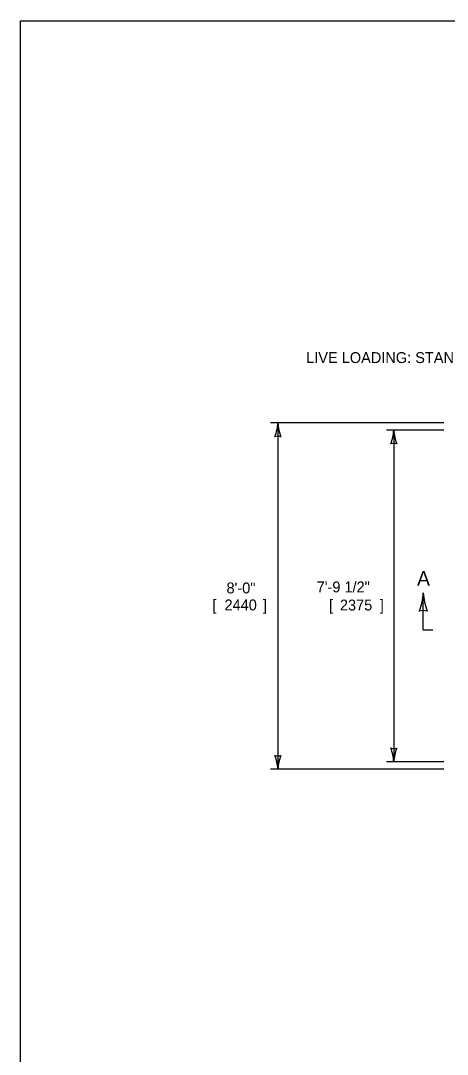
# Model space of a CAD drawing. Extents: x 49991.4 to 50021, y 49987.6 to 50011.4.
# Drawn here: x 49999.38 to 50001.74, y 49993.3 to 49999 of the extents above; entities that cross this region are included whole.
import ezdxf

# ---------------------------------------------------------------- set-up
doc = ezdxf.new("R2010")
doc.units = 0
for name, color, linetype in [('Level 1', 7, 'Continuous'), ('Level 2', 7, 'Continuous'), ('Level 3', 7, 'Continuous'), ('Level 6', 7, 'Continuous')]:
    doc.layers.add(name, color=color, linetype=linetype)

msp = doc.modelspace()

# ---------------------------------------------------------------- linework, layer by layer
at = {"layer": 'Level 1'}
msp.add_lwpolyline([(49999.3835, 49998.9992), (50016.7501, 49998.9992), (50016.7501, 49987.7988), (49999.3835, 49987.7988)], close=True, dxfattribs=at)
at = {"layer": 'Level 3'}
for p, q in [((50001.7187, 49996.781), (50000.7634, 49996.781)), ((50000.8034, 49996.781), (50000.8034, 49994.8717)), ((50001.7187, 49996.741), (50001.403, 49996.741)), ((50001.443, 49996.741), (50001.443, 49994.9122)), ((50001.7187, 49994.8717), (50000.7634, 49994.8717)), ((50001.7187, 49994.9122), (50001.403, 49994.9122))]:
    msp.add_line(p, q, dxfattribs=at)
for centre, radius, start, end in [((50000.5813, 49996.7902), 0.2223, 337.456, 357.6395), ((50001.0362, 49996.7925), 0.233, 182.8273, 202.0772), ((50001.2208, 49996.7502), 0.2223, 337.456, 357.6395), ((50001.6757, 49996.7525), 0.233, 182.8273, 202.0772), ((50000.8034, 49996.6528), 0.0548, 72.1388, 107.8612), ((50001.443, 49996.6128), 0.0548, 72.1388, 107.8612), ((50001.443, 49995.0404), 0.0548, 252.1388, 287.8612), ((50001.2102, 49994.9007), 0.233, 2.8273, 22.0772), ((50001.6651, 49994.903), 0.2223, 157.456, 177.6395), ((50000.8034, 49994.9999), 0.0548, 252.1388, 287.8612), ((50000.5707, 49994.8602), 0.233, 2.8273, 22.0772), ((50001.0256, 49994.8625), 0.2223, 157.456, 177.6395)]:
    msp.add_arc(centre, radius, start, end, dxfattribs=at)
at = {"layer": 'Level 6'}
for q in [(50001.6058, 49995.8437), (50001.6587, 49995.639)]:
    msp.add_line((50001.6058, 49995.639), q, dxfattribs=at)
for centre, radius, start, end in [((50001.3096, 49995.8559), 0.2964, 337.456, 357.6395), ((50001.916, 49995.859), 0.3107, 182.8273, 202.0772), ((50001.6058, 49995.6727), 0.073, 72.1388, 107.8612)]:
    msp.add_arc(centre, radius, start, end, dxfattribs=at)

# ---------------------------------------------------------------- texts
at = {"layer": 'Level 2'}
for s, height, p in [('LIVE LOADING: STANDARD (HS20) LOADING', 0.06, (50000.9594, 49997.1112)), ('A', 0.08, (50001.5714, 49995.8837)), ('8\'-0"', 0.06, (50000.5197, 49995.8408)), ('7\'-9 1/2"', 0.06, (50001.0173, 49995.8466)), ('[', 0.06, (50000.4417, 49995.7472)), ('2440', 0.06, (50000.5086, 49995.7472)), (']', 0.06, (50000.7214, 49995.7472)), ('[', 0.06, (50001.0859, 49995.7466)), ('2375', 0.06, (50001.1457, 49995.7466)), (']', 0.06, (50001.3656, 49995.7466))]:
    msp.add_text(s, height=height, dxfattribs=at).set_placement(p)

doc.saveas('drawing.dxf')
